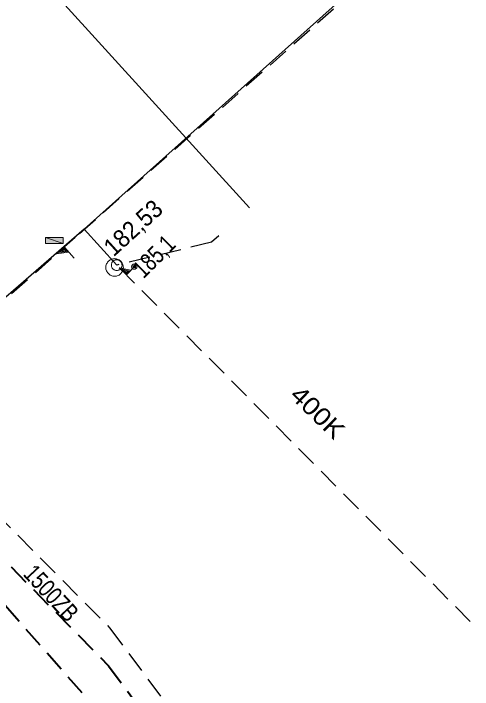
# Model space of a CAD drawing. Extents: x -740851 to -738888, y -1041382 to -1040235.
# Drawn here: x -739692.27 to -739666.27, y -1040586.71 to -1040548.46 of the extents above; entities that cross this region are included whole.
import ezdxf

# ---------------------------------------------------------------- set-up
doc = ezdxf.new("R2010")
doc.units = 0
doc.header["$LTSCALE"] = 0.4
doc.linetypes.add('MEDIUM_DASHED', pattern=[4.5, 3, -1.5])
for name, color, linetype, lineweight in [('18', 7, 'Continuous', 13), ('20', 7, 'MEDIUM_DASHED', 25), ('8', 7, 'Continuous', 13)]:
    doc.layers.add(name, color=color, linetype=linetype, lineweight=lineweight)

msp = doc.modelspace()

# ---------------------------------------------------------------- hatches: boundary and pattern name
at = {"layer": '18'}
msp.add_hatch(color=256, dxfattribs=at).paths.add_polyline_path([(-739690.46, -1040561.13), (-739690.46, -1040561.47), (-739689.46, -1040561.47), (-739689.46, -1040561.13)])

# ---------------------------------------------------------------- linework, layer by layer
at = {"layer": '18', "lineweight": 25}
msp.add_line((-739686.42, -1040562.7), (-739688.27, -1040560.66), dxfattribs=at)
at = {"layer": '18'}
msp.add_line((-739690.46, -1040561.13), (-739689.46, -1040561.47), dxfattribs=at)
at = {"layer": '18', "linetype": 'MEDIUM_DASHED', "lineweight": 25}
msp.add_line((-739666.39, -1040582.87), (-739686.42, -1040562.7), dxfattribs=at)
at = {"layer": '18', "lineweight": 25}
msp.add_lwpolyline([(-739659.45, -1040534.92), (-739688.27, -1040560.66), (-739696.73, -1040567.98)], dxfattribs=at)
at = {"layer": '18'}
for points in [[(-739690.46, -1040561.13), (-739690.46, -1040561.47), (-739689.46, -1040561.47), (-739689.46, -1040561.13)], [(-739686.04, -1040562.83), (-739686.05, -1040562.78), (-739686.05, -1040562.73), (-739686.07, -1040562.68), (-739686.09, -1040562.63), (-739686.11, -1040562.58), (-739686.14, -1040562.54), (-739686.17, -1040562.5), (-739686.21, -1040562.46), (-739686.25, -1040562.43), (-739686.29, -1040562.4), (-739686.34, -1040562.38), (-739686.39, -1040562.36), (-739686.44, -1040562.34), (-739686.49, -1040562.34), (-739686.54, -1040562.33), (-739686.59, -1040562.34), (-739686.64, -1040562.34), (-739686.69, -1040562.36), (-739686.74, -1040562.38), (-739686.79, -1040562.4), (-739686.83, -1040562.43), (-739686.87, -1040562.46), (-739686.91, -1040562.5), (-739686.94, -1040562.54), (-739686.97, -1040562.58), (-739686.99, -1040562.63), (-739687.01, -1040562.68), (-739687.03, -1040562.73), (-739687.03, -1040562.78), (-739687.04, -1040562.83), (-739687.03, -1040562.88), (-739687.03, -1040562.93), (-739687.01, -1040562.98), (-739686.99, -1040563.03), (-739686.97, -1040563.08), (-739686.94, -1040563.12), (-739686.91, -1040563.16), (-739686.87, -1040563.2), (-739686.83, -1040563.23), (-739686.79, -1040563.26), (-739686.74, -1040563.28), (-739686.69, -1040563.3), (-739686.64, -1040563.32), (-739686.59, -1040563.32), (-739686.54, -1040563.33), (-739686.49, -1040563.32), (-739686.44, -1040563.32), (-739686.39, -1040563.3), (-739686.34, -1040563.28), (-739686.29, -1040563.26), (-739686.25, -1040563.23), (-739686.21, -1040563.2), (-739686.17, -1040563.16), (-739686.14, -1040563.12), (-739686.11, -1040563.08), (-739686.09, -1040563.03), (-739686.07, -1040562.98), (-739686.05, -1040562.93), (-739686.05, -1040562.88)], [(-739686.183, -1040562.511), (-739686.202, -1040562.487), (-739686.226, -1040562.467), (-739686.25, -1040562.447), (-739686.278, -1040562.431), (-739686.311, -1040562.419), (-739686.341, -1040562.411), (-739686.37, -1040562.404), (-739686.404, -1040562.4), (-739686.434, -1040562.401), (-739686.464, -1040562.402), (-739686.499, -1040562.407), (-739686.531, -1040562.416), (-739686.558, -1040562.43), (-739686.586, -1040562.444), (-739686.609, -1040562.463), (-739686.633, -1040562.482), (-739686.653, -1040562.506), (-739686.673, -1040562.53), (-739686.689, -1040562.558), (-739686.701, -1040562.591), (-739686.709, -1040562.621), (-739686.716, -1040562.65), (-739686.72, -1040562.684), (-739686.719, -1040562.714), (-739686.718, -1040562.744), (-739686.713, -1040562.779), (-739686.704, -1040562.811), (-739686.69, -1040562.838), (-739686.676, -1040562.866), (-739686.657, -1040562.889), (-739686.638, -1040562.913), (-739686.614, -1040562.933), (-739686.59, -1040562.953), (-739686.562, -1040562.969), (-739686.529, -1040562.981), (-739686.499, -1040562.989), (-739686.47, -1040562.996), (-739686.436, -1040563), (-739686.406, -1040562.999), (-739686.376, -1040562.998), (-739686.341, -1040562.993), (-739686.309, -1040562.984), (-739686.282, -1040562.97), (-739686.254, -1040562.956), (-739686.231, -1040562.937), (-739686.207, -1040562.918), (-739686.187, -1040562.894), (-739686.167, -1040562.87), (-739686.151, -1040562.842), (-739686.139, -1040562.809), (-739686.131, -1040562.779), (-739686.124, -1040562.75), (-739686.12, -1040562.716), (-739686.121, -1040562.686), (-739686.122, -1040562.656), (-739686.127, -1040562.621), (-739686.136, -1040562.589), (-739686.15, -1040562.562), (-739686.164, -1040562.534)]]:
    msp.add_lwpolyline(points, close=True, dxfattribs=at)
for points in [[(-739688.825, -1040562.3), (-739689.378, -1040561.673), (-739689.825, -1040562.068), (-739689.129, -1040561.956)], [(-739689.217, -1040561.922), (-739689.378, -1040561.74), (-739689.664, -1040561.992), (-739689.214, -1040561.919)], [(-739689.308, -1040561.885), (-739689.388, -1040561.794), (-739689.535, -1040561.923), (-739689.305, -1040561.883)], [(-739685.324, -1040562.682), (-739685.873, -1040563.248), (-739686.277, -1040562.857), (-739685.625, -1040562.993)], [(-739685.71, -1040563.021), (-739685.87, -1040563.186), (-739686.128, -1040562.936), (-739685.707, -1040563.023)], [(-739685.797, -1040563.052), (-739685.877, -1040563.134), (-739686.01, -1040563.006), (-739685.795, -1040563.054)]]:
    msp.add_lwpolyline(points, dxfattribs=at)
at = {"layer": '18', "linetype": 'MEDIUM_DASHED', "lineweight": 40}
msp.add_lwpolyline([(-739669.06, -1040610.98), (-739674.7, -1040603.39), (-739681.24, -1040595.01), (-739703.155, -1040570.156)], dxfattribs=at)
at = {"layer": '18'}
for centre, radius in [((-739685.425, -1040562.786), 0.149), ((-739685.425, -1040562.785), 0.0734)]:
    msp.add_circle(centre, radius, dxfattribs=at)
at = {"layer": '20'}
msp.add_lwpolyline([(-739674.14, -1040548.21), (-739688.774, -1040561.14), (-739702.73, -1040573.46)], dxfattribs=at)
at = {"layer": '8', "lineweight": 25}
msp.add_line((-739692.17, -1040544.88), (-739678.904, -1040559.46), dxfattribs=at)
at = {"layer": '8', "linetype": 'MEDIUM_DASHED', "lineweight": 25}
for points in [[(-739680.64, -1040561.04), (-739681.047, -1040561.403), (-739686.42, -1040562.7)], [(-739693.286, -1040576.71), (-739686.808, -1040583.233), (-739625.283, -1040665.839), (-739571.664, -1040740.804), (-739523.94, -1040810.745), (-739502.47, -1040846.1), (-739496.554, -1040855.122)]]:
    msp.add_lwpolyline(points, dxfattribs=at)
at = {"layer": '8', "linetype": 'MEDIUM_DASHED', "lineweight": 40}
msp.add_lwpolyline([(-739697.47, -1040574.66), (-739686.88, -1040585.368), (-739626.36, -1040666.625), (-739572.757, -1040741.567), (-739553.461, -1040769.846), (-739533.944, -1040772.907), (-739491.526, -1040761.298), (-739476.568, -1040755.167), (-739461.603, -1040761.762), (-739415.52, -1040777.67)], dxfattribs=at)

# ---------------------------------------------------------------- texts
at = {"layer": '18'}
for s, rotation, width, p in [('182,53', 42.203, 0.95, (-739686.598, -1040562.262)), ('185,1', 44.777, 0.8, (-739684.904, -1040563.497)), ('400K', 315.8, 1.15, (-739676.672, -1040570.139)), ('1500ZB', 312.869, 0.8, (-739691.768, -1040580.225))]:
    msp.add_text(s, height=1, rotation=rotation, dxfattribs=dict(at, width=width)).set_placement(p)

doc.saveas('drawing.dxf')
